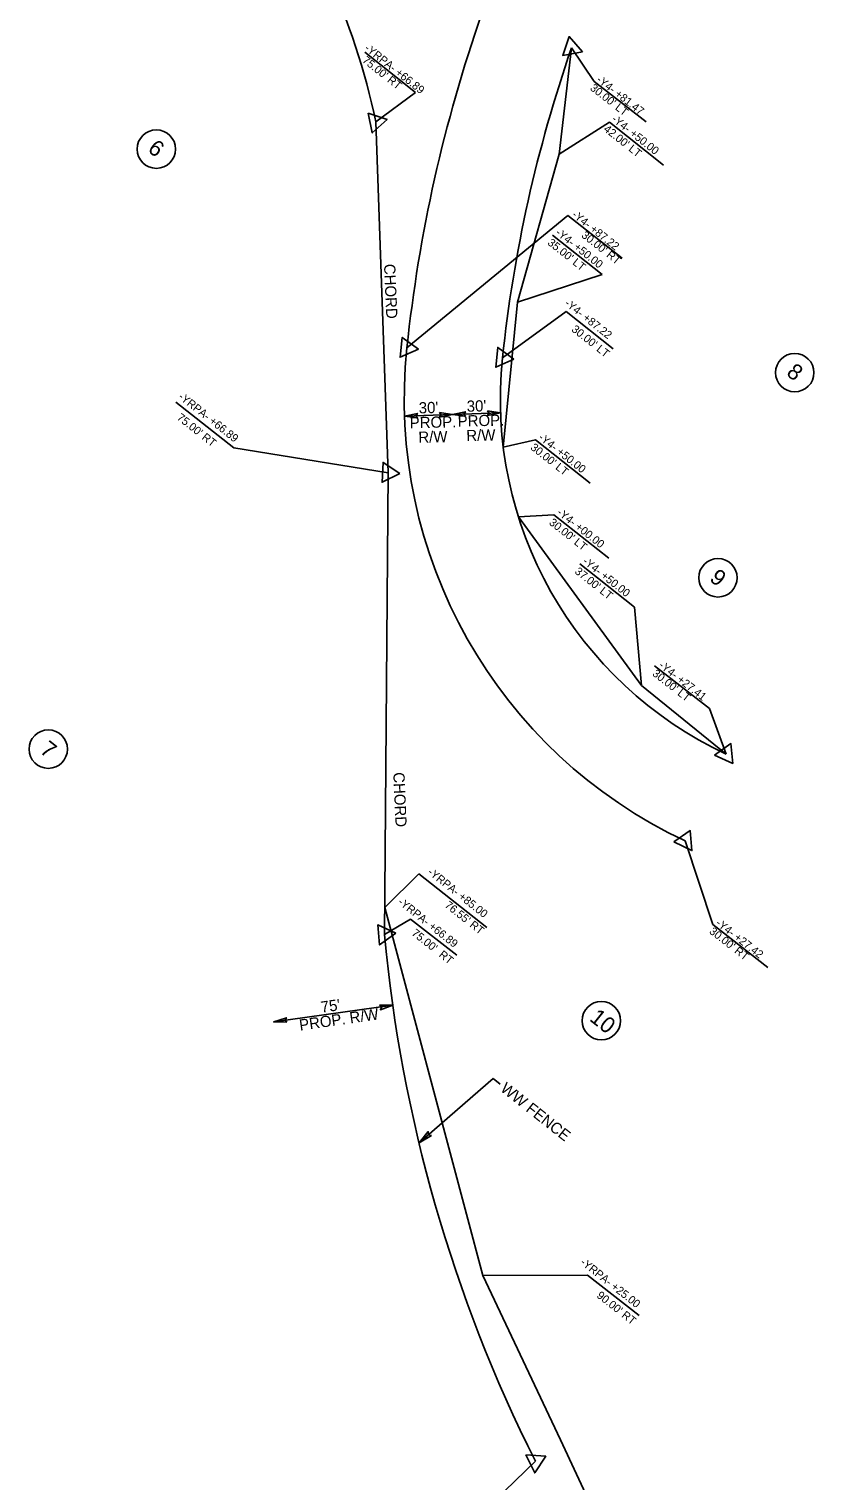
# Model space of a CAD drawing. Extents: x 1779796 to 1783527, y 810952 to 815815.
# Drawn here: x 1782304 to 1782794, y 812750 to 813658 of the extents above; entities that cross this region are included whole.
import ezdxf

# ---------------------------------------------------------------- set-up
doc = ezdxf.new("R2010")
doc.units = 0
for name, color, linetype in [('Prop Dimension', 7, 'Continuous'), ('Prop Dimension Text', 7, 'Continuous'), ('Prop Easement Construction', 7, 'Continuous'), ('Prop Easement Construction Station Offsets', 7, 'Continuous'), ('Prop Fence Woven Wire', 7, 'Continuous'), ('Prop Parcel Number CELL', 7, 'Continuous'), ('Prop Parcel Number Text', 7, 'Continuous'), ('Prop ROW Marker CELL', 7, 'Continuous'), ('Prop ROW RW CA Lines', 7, 'Continuous'), ('Prop ROW RW Lines', 7, 'Continuous'), ('Prop ROW Station Offsets', 7, 'Continuous'), ('Prop Terminator CELL', 7, 'Continuous')]:
    doc.layers.add(name, color=color, linetype=linetype)

msp = doc.modelspace()

# ---------------------------------------------------------------- linework, layer by layer
at = {"layer": 'Prop Dimension'}
for p, q in [((1782538.17, 813415.72), (1782568.16, 813416.77)), ((1782598.14, 813417.83), (1782568.16, 813416.77)), ((1782530.81, 813047.78), (1782456.55, 813037.27)), ((1782547.22, 812961.6), (1782593.49, 813001.87)), ((1782593.49, 813001.87), (1782597.9, 812998.38))]:
    msp.add_line(p, q, dxfattribs=at)
at = {"layer": 'Prop Easement Construction'}
for p, q in [((1782642.46, 813645.77), (1782634.79, 813579.35)), ((1782634.79, 813579.35), (1782608.78, 813487.01)), ((1782608.78, 813487.01), (1782599.85, 813396.24)), ((1782609.32, 813352.77), (1782686.05, 813247.5)), ((1782686.05, 813247.5), (1782738.96, 813204.61)), ((1782525.78, 813108.78), (1782587.11, 812878.72)), ((1782587.11, 812878.72), (1782635.54, 812776.1)), ((1782635.54, 812776.1), (1782668.33, 812706.14))]:
    msp.add_line(p, q, dxfattribs=at)
at = {"layer": 'Prop Easement Construction Station Offsets'}
for p, q in [((1782634.79, 813579.35), (1782666.08, 813599.34)), ((1782699.95, 813572.53), (1782666.08, 813599.34)), ((1782661.53, 813504.29), (1782630.59, 813528.78)), ((1782608.78, 813487.01), (1782661.53, 813504.29)), ((1782599.85, 813396.24), (1782619.91, 813400.84)), ((1782654.09, 813373.78), (1782619.91, 813400.84)), ((1782609.32, 813352.77), (1782631.5, 813353.95)), ((1782665.68, 813326.89), (1782631.5, 813353.95)), ((1782681.72, 813296.36), (1782647.54, 813323.42)), ((1782681.72, 813296.36), (1782686.05, 813247.5)), ((1782525.78, 813108.78), (1782547.15, 813129.85)), ((1782547.15, 813129.85), (1782589.54, 813096.27)), ((1782587.11, 812878.72), (1782652.42, 812878.93)), ((1782652.42, 812878.93), (1782684.77, 812853.91))]:
    msp.add_line(p, q, dxfattribs=at)
at = {"layer": 'Prop Fence Woven Wire'}
for p, q in [((1782520.29, 813599.54), (1782528.06, 813380.39)), ((1782528.06, 813380.39), (1782525.64, 813091.93))]:
    msp.add_line(p, q, dxfattribs=at)
for centre, radius, start, end in [((1782080.1, 813506.06), 450, 11.98935, 36.80105), ((1783446.68, 813177.45), 925, 185.30484, 206.63934)]:
    msp.add_arc(centre, radius, start, end, dxfattribs=at)
at = {"layer": 'Prop Parcel Number CELL'}
for p, q in [((1782383.21, 813582.52), (1782383.21, 813582.52)), ((1782781.82, 813442.91), (1782781.82, 813442.91)), ((1782733.88, 813314.71), (1782733.88, 813314.71)), ((1782315.73, 813207.66), (1782315.73, 813207.66)), ((1782661.08, 813038.01), (1782661.08, 813038.01))]:
    msp.add_line(p, q, dxfattribs=at)
for centre in [(1782383.21, 813582.52), (1782781.82, 813442.91), (1782733.88, 813314.71), (1782315.73, 813207.66), (1782661.08, 813038.01)]:
    msp.add_circle(centre, 12, dxfattribs=at)
at = {"layer": 'Prop ROW Marker CELL'}
for p, q in [((1782642.46, 813645.77), (1782642.46, 813645.77)), ((1782520.29, 813599.54), (1782520.29, 813599.54)), ((1782539.66, 813458.31), (1782539.66, 813458.31)), ((1782599.33, 813452.04), (1782599.33, 813452.04)), ((1782528.06, 813380.39), (1782528.06, 813380.39)), ((1782738.96, 813204.61), (1782738.96, 813204.61)), ((1782713.5, 813150.28), (1782713.5, 813150.28)), ((1782525.64, 813091.93), (1782525.64, 813091.93)), ((1782619.87, 812762.71), (1782619.87, 812762.71))]:
    msp.add_line(p, q, dxfattribs=at)
for points in [[(1782649.27, 813643.41), (1782637.02, 813641.05), (1782641.08, 813652.85)], [(1782515.47, 813604.9), (1782527.33, 813601.03), (1782518.06, 813592.68)], [(1782546.83, 813457.56), (1782535.43, 813452.49), (1782536.71, 813464.9)], [(1782606.5, 813451.29), (1782595.1, 813446.21), (1782596.38, 813458.62)], [(1782535.26, 813379.97), (1782524.12, 813374.36), (1782524.81, 813386.82)], [(1782731.78, 813203.94), (1782741.96, 813211.15), (1782743.14, 813198.73)], [(1782706.3, 813149.73), (1782716.61, 813156.77), (1782717.58, 813144.33)], [(1782532.82, 813092.6), (1782522.64, 813085.39), (1782521.46, 813097.81)], [(1782613.85, 812766.68), (1782626.31, 812765.93), (1782619.46, 812755.51)]]:
    msp.add_lwpolyline(points, close=True, dxfattribs=at)
at = {"layer": 'Prop ROW RW CA Lines'}
for p, q in [((1782520.29, 813599.54), (1782528.06, 813380.39)), ((1782528.06, 813380.39), (1782525.64, 813091.93))]:
    msp.add_line(p, q, dxfattribs=at)
for centre, radius, start, end in [((1782080.1, 813506.06), 450, 11.98935, 36.80105), ((1783446.68, 813177.45), 925, 185.30484, 206.63934)]:
    msp.add_arc(centre, radius, start, end, dxfattribs=at)
at = {"layer": 'Prop ROW RW Lines'}
for centre, radius, start, end in [((1783464.56, 813361.08), 930, 160.79649, 173.99833), ((1783464.56, 813361.08), 870, 160.89936, 173.99833), ((1782842.99, 813426.42), 305, 173.99833, 244.87736), ((1782842.99, 813426.42), 245, 173.99833, 244.87503)]:
    msp.add_arc(centre, radius, start, end, dxfattribs=at)
at = {"layer": 'Prop ROW Station Offsets'}
for p, q in [((1782545.02, 813617.96), (1782513.32, 813643.08)), ((1782642.46, 813645.77), (1782656.59, 813624.86)), ((1782656.59, 813624.86), (1782688.96, 813599.62)), ((1782520.29, 813599.54), (1782545.02, 813617.96)), ((1782539.66, 813458.31), (1782640.05, 813541.01)), ((1782640.05, 813541.01), (1782674.14, 813514.43)), ((1782599.33, 813452.04), (1782639.14, 813481.03)), ((1782639.14, 813481.03), (1782668.52, 813457.75)), ((1782431.68, 813395.82), (1782395.42, 813424.54)), ((1782528.06, 813380.39), (1782431.68, 813395.82)), ((1782728.5, 813233.13), (1782694.35, 813259.76)), ((1782738.96, 813204.61), (1782728.5, 813233.13)), ((1782713.5, 813150.28), (1782730.72, 813098.04)), ((1782525.64, 813091.93), (1782541.87, 813101.52)), ((1782541.87, 813101.52), (1782570.74, 813079)), ((1782730.72, 813098.04), (1782765.08, 813071.25)), ((1782619.87, 812762.71), (1782600.8, 812744.36))]:
    msp.add_line(p, q, dxfattribs=at)
at = {"layer": 'Prop Terminator CELL'}
for points in [[(1782546.32, 813414.61), (1782538.17, 813415.72), (1782546.26, 813417.45), (1782545.28, 813415.97)], [(1782560.01, 813417.88), (1782568.16, 813416.77), (1782560.07, 813415.05), (1782561.05, 813416.52)], [(1782576.3, 813415.66), (1782568.16, 813416.77), (1782576.24, 813418.5), (1782575.26, 813417.02)], [(1782589.99, 813418.94), (1782598.14, 813417.83), (1782590.05, 813416.1), (1782591.03, 813417.58)], [(1782464.77, 813037.03), (1782456.55, 813037.27), (1782464.42, 813039.84), (1782463.59, 813038.27)], [(1782522.6, 813047.62), (1782530.81, 813047.78), (1782523.09, 813044.83), (1782523.83, 813046.44)], [(1782555.02, 812966.33), (1782547.22, 812961.6), (1782552.99, 812968.74), (1782553.18, 812966.78)]]:
    msp.add_lwpolyline(points, close=True, dxfattribs=at)

# ---------------------------------------------------------------- texts
at = {"layer": 'Prop Dimension Text'}
for s, rotation, p in [('CHORD', 272.49141, (1782525.34, 813510.7)), ("30'", 1.38637, (1782547.14, 813417.4)), ("30'", 1.38637, (1782577.09, 813418.43)), ('PROP.', 1.38637, (1782541.49, 813408.08)), ('PROP.', 1.38637, (1782571.43, 813409.11)), ('R/W', 1.38637, (1782546.88, 813399.03)), ('R/W', 1.38637, (1782576.82, 813400.06)), ('CHORD', 272.49141, (1782531.13, 813193.09)), ("75' ", 8.23848, (1782486.38, 813042.92)), ('PROP. R/W', 8.23848, (1782472.96, 813031.71)), ('WW FENCE', 321.63093, (1782597.54, 812994.5))]:
    msp.add_text(s, height=7, rotation=rotation, dxfattribs=at).set_placement(p)
at = {"layer": 'Prop Easement Construction Station Offsets'}
for s, rotation, p in [('-Y4- +50.00', 321.63093, (1782667.03, 813600.5)), ("42.00' LT", 321.63093, (1782662.06, 813594.23)), ('-Y4- +50.00', 321.63093, (1782632.06, 813529.54)), ("35.00' LT", 321.63093, (1782627.09, 813523.26)), ('-Y4- +50.00', 321.63093, (1782621.37, 813401.59)), ("30.00' LT", 321.63093, (1782616.41, 813395.32)), ('-Y4- +00.00', 321.63093, (1782632.96, 813354.7)), ("30.00' LT", 321.63093, (1782628, 813348.43)), ("37.00' LT", 321.63093, (1782644.04, 813317.91)), ('-Y4- +50.00', 321.63093, (1782649, 813324.18)), ('-YRPA- +85.00', 321.61668, (1782552.22, 813130)), ("76.55' RT", 321.61668, (1782562.84, 813109.37)), ('-YRPA- +25.00', 321.61668, (1782647.51, 812886.25)), ("90.00' RT", 321.61668, (1782657.75, 812865.53))]:
    msp.add_text(s, height=5, rotation=rotation, dxfattribs=at).set_placement(p)
at = {"layer": 'Prop Parcel Number Text'}
for s, p in [('6', (1782377.23, 813581.51)), ('8', (1782776.03, 813441.76)), ('9', (1782728.05, 813313.27)), ('7', (1782309.94, 813205.87)), ('10', (1782653.13, 813038.45))]:
    msp.add_text(s, height=10, rotation=321.63093, dxfattribs=at).set_placement(p)
at = {"layer": 'Prop ROW RW Lines'}
for s, p in [("30.00' LT", (1782653.58, 813619.9)), ('-Y4- +81.47', (1782657.61, 813625.07)), ('-Y4- +27.41', (1782696.52, 813259.21)), ("30.00' LT", (1782692.49, 813254.04)), ("30.00' RT", (1782728.05, 813092.99)), ('-Y4- +27.42', (1782732.08, 813098.16))]:
    msp.add_text(s, height=5, rotation=322.05456, dxfattribs=at).set_placement(p)
at = {"layer": 'Prop ROW Station Offsets'}
for s, rotation, p in [("75.00' RT", 321.61668, (1782511.39, 813637.23)), ('-YRPA- +66.89', 321.61668, (1782512.8, 813644.72)), ('-Y4- +87.22', 321.61668, (1782642.25, 813540.76)), ("30.00' RT", 321.61668, (1782648.22, 813527.94)), ('-Y4- +87.22', 321.61002, (1782637.7, 813485.36)), ("30.00' LT", 321.61002, (1782642.03, 813469.17)), ('-YRPA- +66.89', 321.61668, (1782396.57, 813427.06)), ("75.00' RT", 321.61668, (1782395.62, 813414.01)), ('-YRPA- +66.89', 321.61668, (1782533.63, 813111.35)), ("75.00'  RT", 321.61668, (1782542.19, 813091.91))]:
    msp.add_text(s, height=5, rotation=rotation, dxfattribs=at).set_placement(p)

doc.saveas('drawing.dxf')
